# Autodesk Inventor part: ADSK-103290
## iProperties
Shininess: 0.0
Created: 2000-04
Part Number: ADSK-103290
Document SubType Name: Modeling
Stock Number: ADSK-103290
Density: 1 g/cm^3
Density: 0.0
Volumn: 0.0
Area: 0.0
PropertySet Name: Model Information
Control State: 0
Checked Out: False
Master: False
Author: gao
